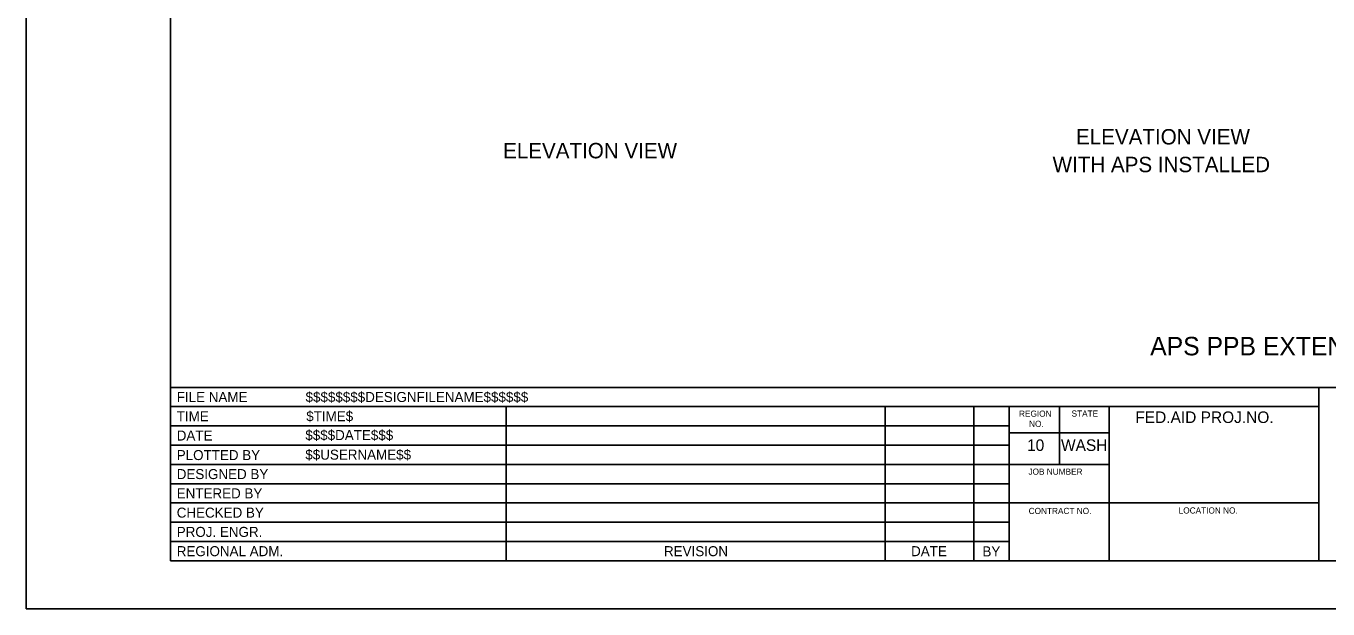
# Model space of a CAD drawing. Extents: x 99999.1 to 100016.1, y 99999.7 to 100010.7.
# Drawn here: x 99999.06 to 100007.52, y 99999.69 to 100003.47 of the extents above; entities that cross this region are included whole.
import ezdxf

# ---------------------------------------------------------------- set-up
doc = ezdxf.new("R2010")
doc.units = 0
for name, color, linetype in [('Level 20', 7, 'Continuous'), ('SH_GI_PlotLimits', 7, 'Continuous'), ('SH_GI_SheetBorder', 7, 'Continuous'), ('SH_GI_SheetTextInCells', 7, 'Continuous'), ('SH_GI_TitleBlockText', 7, 'Continuous')]:
    doc.layers.add(name, color=color, linetype=linetype)

msp = doc.modelspace()

# ---------------------------------------------------------------- linework, layer by layer
at = {"layer": 'SH_GI_PlotLimits'}
msp.add_lwpolyline([(99999.0625, 99999.6875), (100016.0625, 99999.6875), (100016.0625, 100010.6875), (99999.0625, 100010.6875)], close=True, dxfattribs=at)
at = {"layer": 'SH_GI_SheetBorder'}
for p, q in [((100000, 100010.375), (100000, 100000)), ((100000, 100001.1259), (100015.75, 100001.1259)), ((100007.4566, 100000), (100007.4566, 100001.1259)), ((100000, 100001.0008), (100007.4566, 100001.0008)), ((100002.179, 100001.0008), (100002.179, 100000)), ((100004.641, 100001.0008), (100004.641, 100000)), ((100005.2164, 100001.0008), (100005.2164, 100000)), ((100005.4451, 100001.0008), (100005.4451, 100000)), ((100005.7719, 100000.6255), (100005.7719, 100001.0008)), ((100006.0956, 100000), (100006.0956, 100001.0008)), ((100000, 100000.8757), (100002.1821, 100000.8757)), ((100002.1821, 100000.8757), (100005.4466, 100000.8757)), ((100006.0958, 100000.831), (100005.4466, 100000.831)), ((100000, 100000.7506), (100002.1821, 100000.7506)), ((100002.1821, 100000.7506), (100005.4466, 100000.7506)), ((100000, 100000.6255), (100005.4466, 100000.6255)), ((100006.0958, 100000.6255), (100005.4466, 100000.6255)), ((100000, 100000.5004), (100005.4466, 100000.5004)), ((100000, 100000.3753), (100005.4466, 100000.3753)), ((100007.4566, 100000.3753), (100005.4466, 100000.3753)), ((100000, 100000.2502), (100005.4466, 100000.2502)), ((100000, 100000.1251), (100005.4466, 100000.1251)), ((100000, 100000), (100015.75, 100000))]:
    msp.add_line(p, q, dxfattribs=at)

# ---------------------------------------------------------------- texts
at = {"layer": 'Level 20'}
for s, height, p in [('ELEVATION VIEW', 0.1, (100005.8798, 100002.7024)), ('ELEVATION VIEW', 0.1, (100002.16, 100002.6124)), ('WITH APS INSTALLED', 0.1, (100005.728, 100002.5224)), ('APS PPB EXTENSION DETAIL', 0.12, (100006.3617, 100001.3336))]:
    msp.add_text(s, height=height, dxfattribs=at).set_placement(p)
at = {"layer": 'SH_GI_SheetTextInCells'}
for s, height, p in [('FILE NAME', 0.06505, (100000.041, 100001.0308)), ('TIME', 0.06505, (100000.041, 100000.9057)), ('REGION', 0.04003, (100005.5099, 100000.9352)), ('STATE', 0.04003, (100005.8511, 100000.9357)), ('FED.AID PROJ.NO.', 0.07506, (100006.2652, 100000.8945)), ('NO.', 0.04003, (100005.5752, 100000.869)), ('DATE', 0.06505, (100000.041, 100000.7806)), ('PLOTTED BY', 0.06505, (100000.041, 100000.6538)), ('10', 0.07506, (100005.5621, 100000.7131)), ('WASH', 0.07506, (100005.7826, 100000.7131)), ('DESIGNED BY', 0.065052, (100000.041, 100000.5304)), ('JOB NUMBER', 0.04003, (100005.5712, 100000.5587)), ('ENTERED BY', 0.06505, (100000.041, 100000.4053)), ('CHECKED BY', 0.06505, (100000.041, 100000.2802)), ('CONTRACT NO.', 0.040032, (100005.5725, 100000.3037)), ('LOCATION NO.', 0.040032, (100006.5465, 100000.3067)), ('PROJ. ENGR.', 0.065052, (100000.041, 100000.1551)), ('REGIONAL ADM.', 0.065052, (100000.041, 100000.03)), ('REVISION', 0.06505, (100003.2048, 100000.03)), ('DATE', 0.06505, (100004.8091, 100000.03)), ('BY', 0.06505, (100005.2725, 100000.0285))]:
    msp.add_text(s, height=height, dxfattribs=at).set_placement(p)
at = {"layer": 'SH_GI_TitleBlockText'}
for s, height, p in [('$$$$$$$$DESIGNFILENAME$$$$$$', 0.065052, (100000.8775, 100001.0308)), ('$TIME$', 0.06505, (100000.882, 100000.9059)), ('$$$$DATE$$$', 0.065052, (100000.8759, 100000.7835)), ('$$USERNAME$$', 0.065052, (100000.8759, 100000.6567))]:
    msp.add_text(s, height=height, dxfattribs=at).set_placement(p)

doc.saveas('drawing.dxf')
